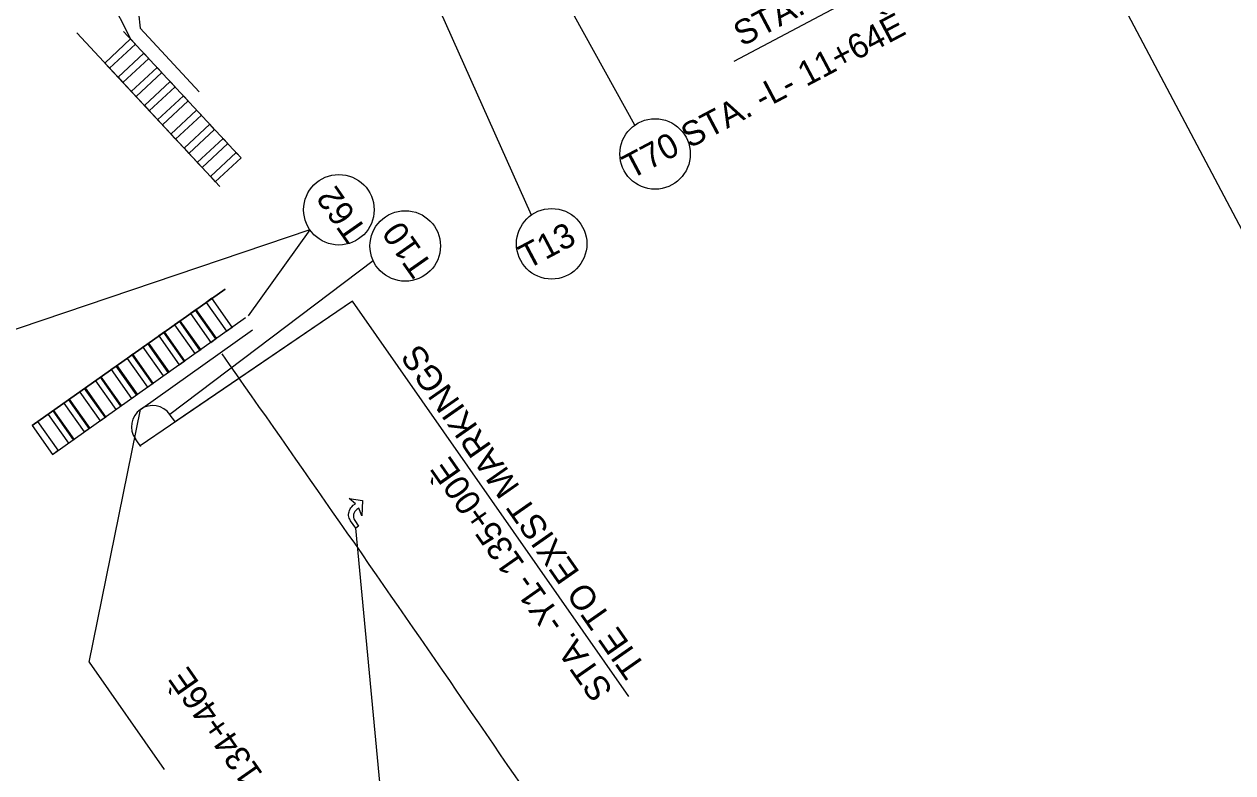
# Model space of a CAD drawing. Extents: x 1487421 to 1489048, y 497792 to 499463.
# Drawn here: x 1487756.3 to 1488099.3, y 498179.4 to 498391.7 of the extents above; entities that cross this region are included whole.
import ezdxf

# ---------------------------------------------------------------- set-up
doc = ezdxf.new("R2010")
doc.units = 0
for name, color, linetype in [('MARK RIGHT ONLY RIGHT SYMBOL CELL', 7, 'Continuous'), ('Prop Mkg Solid White Crosswalks', 7, 'Continuous'), ('Prop Mkg Solid White Edge Line', 7, 'Continuous'), ('Prop Mkg Solid White Stop Bar', 7, 'Continuous'), ('Prop Mkg Solid Yellow Edge Line', 7, 'Continuous'), ('Scratch_Level_2', 7, 'Continuous'), ('Scratch_Level_5', 7, 'Continuous'), ('Scratch_Level_6', 7, 'Continuous'), ('Text', 7, 'Continuous')]:
    doc.layers.add(name, color=color, linetype=linetype)

msp = doc.modelspace()

# ---------------------------------------------------------------- linework, layer by layer
at = {"layer": 'MARK RIGHT ONLY RIGHT SYMBOL CELL'}
msp.add_lwpolyline([(1487851.23, 498249.35), (1487850.41, 498248.78), (1487848.94, 498250.91), (1487848.69, 498251.32), (1487848.54, 498251.65), (1487848.42, 498252.05), (1487848.38, 498252.42), (1487848.38, 498252.72), (1487848.42, 498253.16), (1487848.51, 498253.48), (1487848.62, 498253.85), (1487848.81, 498254.26), (1487849, 498254.55), (1487849.28, 498254.89), (1487849.71, 498255.29), (1487850.37, 498255.74), (1487848.55, 498257.22), (1487852.35, 498256.69), (1487852.14, 498252.3), (1487851.27, 498254.44), (1487850.72, 498254.06), (1487850.43, 498253.83), (1487850.19, 498253.56), (1487850.05, 498253.3), (1487849.88, 498252.94), (1487849.79, 498252.65), (1487849.76, 498252.22), (1487849.81, 498251.8), (1487849.91, 498251.41), (1487850.15, 498250.93)], close=True, dxfattribs=at)
at = {"layer": 'Prop Mkg Solid White Crosswalks'}
for p, q in [((1487771.26, 498389.28), (1487811.8, 498345.68)), ((1487784.54, 498389.68), (1487816.99, 498354.78)), ((1487779.21, 498380.73), (1487786.53, 498387.54)), ((1487786.53, 498387.54), (1487779.21, 498380.73)), ((1487780.57, 498379.26), (1487787.89, 498386.07)), ((1487780.57, 498379.26), (1487787.89, 498386.07)), ((1487787.89, 498386.07), (1487786.53, 498387.54)), ((1487782.95, 498376.7), (1487790.27, 498383.51)), ((1487790.27, 498383.51), (1487782.95, 498376.7)), ((1487791.64, 498382.05), (1487790.27, 498383.51)), ((1487779.21, 498380.73), (1487780.57, 498379.26)), ((1487784.31, 498375.24), (1487791.64, 498382.05)), ((1487784.31, 498375.24), (1487791.64, 498382.05)), ((1487786.7, 498372.67), (1487794.02, 498379.48)), ((1487794.02, 498379.48), (1487786.7, 498372.67)), ((1487795.38, 498378.02), (1487794.02, 498379.48)), ((1487782.95, 498376.7), (1487784.31, 498375.24)), ((1487788.06, 498371.21), (1487795.38, 498378.02)), ((1487788.06, 498371.21), (1487795.38, 498378.02)), ((1487790.44, 498368.65), (1487797.77, 498375.46)), ((1487797.77, 498375.46), (1487790.44, 498368.65)), ((1487799.13, 498373.99), (1487797.77, 498375.46)), ((1487786.7, 498372.67), (1487788.06, 498371.21)), ((1487791.81, 498367.18), (1487799.13, 498373.99)), ((1487791.81, 498367.18), (1487799.13, 498373.99)), ((1487790.44, 498368.65), (1487791.81, 498367.18)), ((1487794.19, 498364.62), (1487801.51, 498371.43)), ((1487801.51, 498371.43), (1487794.19, 498364.62)), ((1487794.19, 498364.62), (1487801.51, 498371.43)), ((1487795.55, 498363.15), (1487802.87, 498369.96)), ((1487795.55, 498363.15), (1487802.87, 498369.96)), ((1487795.55, 498363.15), (1487802.87, 498369.96)), ((1487802.87, 498369.96), (1487801.51, 498371.43)), ((1487797.93, 498360.59), (1487805.26, 498367.4)), ((1487805.26, 498367.4), (1487797.93, 498360.59)), ((1487799.3, 498359.13), (1487806.62, 498365.94)), ((1487799.3, 498359.13), (1487806.62, 498365.94)), ((1487806.62, 498365.94), (1487805.26, 498367.4)), ((1487794.19, 498364.62), (1487795.55, 498363.15)), ((1487801.68, 498356.56), (1487809, 498363.37)), ((1487809, 498363.37), (1487801.68, 498356.56)), ((1487803.04, 498355.1), (1487810.36, 498361.91)), ((1487803.04, 498355.1), (1487810.36, 498361.91)), ((1487810.36, 498361.91), (1487809, 498363.37)), ((1487797.93, 498360.59), (1487799.3, 498359.13)), ((1487805.43, 498352.54), (1487812.75, 498359.35)), ((1487812.75, 498359.35), (1487805.43, 498352.54)), ((1487814.11, 498357.88), (1487812.75, 498359.35)), ((1487801.68, 498356.56), (1487803.04, 498355.1)), ((1487806.79, 498351.07), (1487814.11, 498357.88)), ((1487806.79, 498351.07), (1487814.11, 498357.88)), ((1487809.17, 498348.51), (1487816.49, 498355.32)), ((1487816.49, 498355.32), (1487809.17, 498348.51)), ((1487817.86, 498353.85), (1487816.49, 498355.32)), ((1487805.43, 498352.54), (1487806.79, 498351.07)), ((1487810.53, 498347.04), (1487817.86, 498353.85)), ((1487810.53, 498347.04), (1487817.86, 498353.85)), ((1487809.17, 498348.51), (1487810.53, 498347.04)), ((1487758.59, 498277.88), (1487813.32, 498316.63)), ((1487809.6, 498314), (1487807.97, 498312.84)), ((1487815.38, 498305.84), (1487809.6, 498314)), ((1487805.11, 498310.82), (1487803.48, 498309.67)), ((1487810.67, 498302.5), (1487804.89, 498310.67)), ((1487810.89, 498302.66), (1487805.11, 498310.82)), ((1487807.97, 498312.84), (1487813.74, 498304.68)), ((1487764.37, 498269.72), (1487819.16, 498308.52)), ((1487800.62, 498307.64), (1487798.99, 498306.49)), ((1487806.18, 498299.33), (1487800.4, 498307.49)), ((1487806.4, 498299.48), (1487800.62, 498307.64)), ((1487803.48, 498309.67), (1487809.26, 498301.5)), ((1487796.13, 498304.46), (1487794.5, 498303.31)), ((1487801.69, 498296.15), (1487795.91, 498304.31)), ((1487801.91, 498296.3), (1487796.13, 498304.46)), ((1487798.99, 498306.49), (1487804.77, 498298.33)), ((1487813.74, 498304.68), (1487815.38, 498305.84)), ((1487791.64, 498301.29), (1487790.01, 498300.13)), ((1487790.01, 498300.13), (1487795.79, 498291.97)), ((1487797.2, 498292.97), (1487791.42, 498301.13)), ((1487797.42, 498293.13), (1487791.64, 498301.29)), ((1487794.5, 498303.31), (1487800.28, 498295.15)), ((1487809.26, 498301.5), (1487810.89, 498302.66)), ((1487787.15, 498298.11), (1487785.52, 498296.95)), ((1487785.52, 498296.95), (1487791.3, 498288.79)), ((1487792.71, 498289.79), (1487786.93, 498297.95)), ((1487792.93, 498289.95), (1487787.15, 498298.11)), ((1487792.93, 498289.95), (1487787.15, 498298.11)), ((1487804.77, 498298.33), (1487806.4, 498299.48)), ((1487782.67, 498294.93), (1487781.03, 498293.77)), ((1487781.03, 498293.77), (1487786.81, 498285.61)), ((1487788.22, 498286.61), (1487782.45, 498294.77)), ((1487788.44, 498286.77), (1487782.67, 498294.93)), ((1487795.79, 498291.97), (1487797.42, 498293.13)), ((1487800.28, 498295.15), (1487801.91, 498296.3)), ((1487778.18, 498291.75), (1487776.55, 498290.6)), ((1487776.55, 498290.6), (1487782.32, 498282.43)), ((1487783.74, 498283.43), (1487777.96, 498291.6)), ((1487783.96, 498283.59), (1487778.18, 498291.75)), ((1487791.3, 498288.79), (1487792.93, 498289.95)), ((1487773.69, 498288.57), (1487772.06, 498287.42)), ((1487772.06, 498287.42), (1487777.84, 498279.26)), ((1487779.25, 498280.26), (1487773.47, 498288.42)), ((1487779.47, 498280.41), (1487773.69, 498288.57)), ((1487786.81, 498285.61), (1487788.44, 498286.77)), ((1487769.2, 498285.39), (1487767.57, 498284.24)), ((1487767.57, 498284.24), (1487773.35, 498276.08)), ((1487774.76, 498277.08), (1487768.98, 498285.24)), ((1487774.98, 498277.23), (1487769.2, 498285.39)), ((1487782.32, 498282.43), (1487783.96, 498283.59)), ((1487764.71, 498282.22), (1487763.08, 498281.06)), ((1487763.08, 498281.06), (1487768.86, 498272.9)), ((1487770.27, 498273.9), (1487764.49, 498282.06)), ((1487770.49, 498274.06), (1487764.71, 498282.22)), ((1487777.84, 498279.26), (1487779.47, 498280.41)), ((1487760.22, 498279.04), (1487758.59, 498277.88)), ((1487758.59, 498277.88), (1487764.37, 498269.72)), ((1487766, 498270.88), (1487760.22, 498279.04)), ((1487773.35, 498276.08), (1487774.98, 498277.23)), ((1487768.86, 498272.9), (1487770.49, 498274.06)), ((1487764.37, 498269.72), (1487766, 498270.88))]:
    msp.add_line(p, q, dxfattribs=at)
at = {"layer": 'Prop Mkg Solid White Edge Line'}
msp.add_arc((1479623.58, 492519.58), 10022.5, 33.876157, 35.209476, dxfattribs=at)
at = {"layer": 'Prop Mkg Solid White Stop Bar'}
for p, q in [((1487805.98, 498372.56), (1487789.23, 498390.59)), ((1487789.31, 498282.48), (1487821.14, 498305.02))]:
    msp.add_line(p, q, dxfattribs=at)
at = {"layer": 'Prop Mkg Solid Yellow Edge Line'}
for centre, radius, start, end in [((1487792.77, 498277.58), 6, 35.1778, 215.1778), ((1479623.58, 492519.58), 10000.5, 35.163427, 35.177837), ((1479623.58, 492519.58), 9988.5, 35.162646, 35.177837)]:
    msp.add_arc(centre, radius, start, end, dxfattribs=at)
at = {"layer": 'Scratch_Level_2'}
msp.add_line((1487927.34, 498663.1), (1488114.48, 498309.57), dxfattribs=at)
at = {"layer": 'Scratch_Level_5'}
for p, q in [((1487779.21, 498380.73), (1487811.8, 498345.68)), ((1487813.32, 498316.63), (1487758.59, 498277.88))]:
    msp.add_line(p, q, dxfattribs=at)
at = {"layer": 'Scratch_Level_6'}
msp.add_line((1487957.78, 498381.29), (1488046.62, 498428.2), dxfattribs=at)
at = {"layer": 'Text'}
for p, q in [((1487780.49, 498473.16), (1487789.23, 498390.59)), ((1487761.79, 498436.13), (1487786.53, 498387.54)), ((1487929.6, 498363.11), (1487894.24, 498426.95)), ((1487900.25, 498337.62), (1487869.63, 498406.26)), ((1487837.42, 498333.39), (1487736.51, 498299.3)), ((1487837.42, 498333.39), (1487819.87, 498309.02)), ((1487855.36, 498324.67), (1487797.67, 498281.03)), ((1487849.53, 498313.16), (1487789.22, 498272.18)), ((1487849.53, 498313.16), (1487799.12, 498278.98)), ((1487927.87, 498201.1), (1487849.53, 498313.16)), ((1487774.74, 498210.83), (1487789.31, 498282.48)), ((1487860.86, 498139.07), (1487850.41, 498248.78)), ((1487774.74, 498210.83), (1487796.03, 498180.39))]:
    msp.add_line(p, q, dxfattribs=at)
for centre in [(1487935.36, 498354.94), (1487845.62, 498339.11), (1487864.45, 498328.84), (1487906.01, 498329.45)]:
    msp.add_circle(centre, 10, dxfattribs=at)

# ---------------------------------------------------------------- texts
at = {"layer": 'Scratch_Level_6'}
msp.add_text('STA. -L- 13+50È', height=7, rotation=27.835, dxfattribs=at).set_placement((1487960.03, 498385.29))
at = {"layer": 'Text'}
for s, rotation, p in [('T70 STA. -L- 11+64È', 27.835, (1487928.58, 498347.67)), ('T62', 124.9556, (1487853.87, 498333.19)), ('T10', 124.9556, (1487872.52, 498323.22)), ('T13', 27.835, (1487899.17, 498322.14)), ('TIE TO EXIST MARKINGS', 124.9554, (1487932.95, 498209.36)), ('STA. -Y1- 135+00È', 124.9554, (1487923.62, 498202.84)), ('T71 STA. -Y1- 134+46È', 124.9556, (1487860.02, 498127.9))]:
    msp.add_text(s, height=7, rotation=rotation, dxfattribs=at).set_placement(p)

doc.saveas('drawing.dxf')
